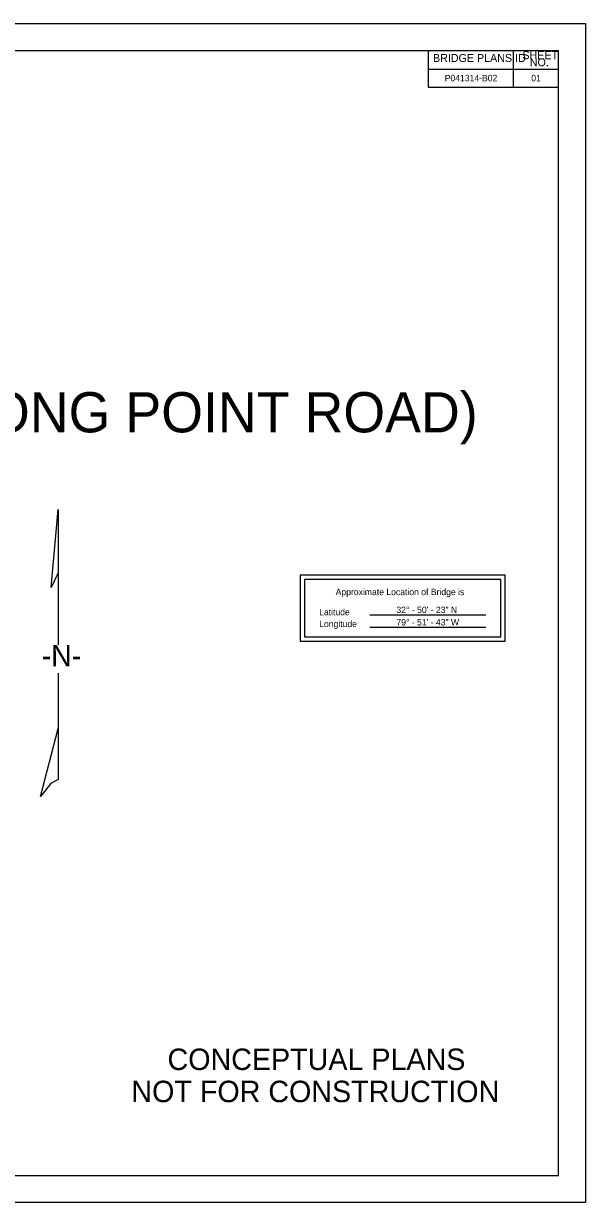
# Model space of a CAD drawing. Extents: x 291 to 2091, y 224 to 1324.
# Drawn here: x 1567 to 2091, y 224 to 1324 of the extents above; entities that cross this region are included whole.
import ezdxf

# ---------------------------------------------------------------- set-up
doc = ezdxf.new("R2010")
doc.units = 0
for name, color, linetype in [('BR_BORDER LINES', 7, 'Continuous'), ('BR_TEXT', 7, 'Continuous'), ('Default', 7, 'Continuous'), ('GN_TitleSheetMap', 7, 'Continuous'), ('RD_SHT_IplotShp', 7, 'Continuous')]:
    doc.layers.add(name, color=color, linetype=linetype)

msp = doc.modelspace()

# ---------------------------------------------------------------- linework, layer by layer
at = {"layer": 'BR_BORDER LINES'}
for p, q in [((391.1, 1299), (2066.1, 1299)), ((1944.4, 1299), (1944.4, 1264.8)), ((2023.9, 1264.8), (2023.9, 1299)), ((2066.1, 249.1), (2066.1, 1299)), ((1944.4, 1281.5), (2066.1, 1281.5)), ((2066.1, 1240.8), (2066.1, 1265.7)), ((1944.4, 1264.8), (2066.1, 1264.8)), ((2066.1, 888.4), (2066.1, 1240.8)), ((391.1, 249.1), (2066.1, 249.1))]:
    msp.add_line(p, q, dxfattribs=at)
at = {"layer": 'BR_TEXT'}
for points in [[(2016.1, 809.3), (1825, 809.3), (1825, 747.7), (2016.1, 747.7)], [(2012.1, 805.3), (1829, 805.3), (1829, 751.7), (2012.1, 751.7)]]:
    msp.add_lwpolyline(points, close=True, dxfattribs=at)
at = {"layer": 'Default'}
for p, q in [((1592.6, 797.9), (1599.3, 870.7)), ((1599.3, 870.7), (1599.3, 811.4)), ((1599.3, 811.4), (1592.6, 797.9)), ((1599.3, 811.4), (1599.3, 770.3)), ((1599.3, 770.3), (1599.3, 744.1)), ((1599.3, 718), (1599.3, 666.2)), ((1582.8, 602.7), (1599.3, 666.2)), ((1599.3, 666.2), (1599.3, 658.3)), ((1599.3, 658.3), (1599.3, 618.6))]:
    msp.add_line(p, q, dxfattribs=at)
msp.add_lwpolyline([(1599.3, 618.6), (1592.2, 614.8), (1582.8, 602.7)], dxfattribs=at)
at = {"layer": 'GN_TitleSheetMap'}
for p, q in [((1890, 772.3), (1998.1, 772.3)), ((1890, 760.7), (1998.1, 760.7))]:
    msp.add_line(p, q, dxfattribs=at)
at = {"layer": 'RD_SHT_IplotShp'}
msp.add_lwpolyline([(291.1, 1324), (2091.1, 1324), (2091.1, 224), (291.1, 224)], close=True, dxfattribs=at)

# ---------------------------------------------------------------- texts
at = {"layer": 'BR_TEXT'}
for s, height, p in [('SHEET', 7.47, (2032.3, 1290.8)), ('BRIDGE PLANS ID', 7.466, (1948.9, 1288.2)), ('NO.', 7.47, (2039.2, 1284.2)), ('CONSTRUCT BRIDGE OVER S-97 (LONG POINT ROAD)', 37.5, (678.3, 942.6)), ('Approximate Location of Bridge is', 6, (1858.1, 790.7)), ('Latitude', 6, (1842.7, 771.9)), ('32%%D - 50\' - 23" N', 6, (1914.8, 774)), ('Longitude', 6, (1842.7, 760.9)), ('79%%D - 51\' - 43" W', 6, (1914.8, 762.4)), ('CONCEPTUAL PLANS', 20, (1701.2, 347.6)), ('NOT FOR CONSTRUCTION', 20, (1667.5, 317.6))]:
    msp.add_text(s, height=height, dxfattribs=at).set_placement(p)
for s, height, p in [('P041314-B02', 5.999, (1959.8, 1270.2)), ('01', 6, (2040.6, 1270.2))]:
    msp.add_text(s, height=height, rotation=0.0002, dxfattribs=at).set_placement(p)
at = {"layer": 'Default'}
msp.add_text('-N-', height=20, dxfattribs=at).set_placement((1583.7, 724.3))

doc.saveas('drawing.dxf')
